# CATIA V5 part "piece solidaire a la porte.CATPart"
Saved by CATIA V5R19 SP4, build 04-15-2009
Part number: element accroché à la porte
Bounding box of the stored display mesh (mm): x -13.29 to 168.34, y -68.462 to 68.538, z -27 to 86.972
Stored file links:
  G:\EU_thinkMotion\CFAO_2010\MMS_groupe1\MMS_groupe1\A reprendre\OK\rdeneffle\piece solidaire a la porte.CATPart
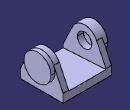
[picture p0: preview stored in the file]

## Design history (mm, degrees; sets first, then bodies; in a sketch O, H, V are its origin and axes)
Parameters
  `rayon element accroché a la porte` = 43 mm
  `rayon axe engrenage` = 21.1 mm
  LENGTH = 0 mm
Body1 (main body)
  Sketch1 on yz-plane, origin (0, 0, 0), H (0, 1, 0), V (0, 0, 1)
    line L1 (-68.4617, -27) -> (68.5383, -27)
    line L2 (68.5383, -27) -> (68.5383, 0)
    point P3 (68.5383, 0)
    line L3 (68.5383, 0) -> (38.8771, 62.4257)
    point P4 (68.5383, 0)
    point P5 (38.8771, 62.4257)
    arc A1 centre (0.0383, 43.9717) radius 43 from (-38.8005, 62.4257) to (38.8771, 62.4257) cw
    point P7 (0.0383, 43.9717)
    point P8 (38.8771, 62.4257)
    line L4 (-68.4617, -27) -> (-68.4617, 0)
    line L5 (-68.4617, 0) -> (-38.8005, 62.4257)
    length L1 = 137
    length L2 = 27
    radius A1 = 43 {= `rayon element accroché a la porte`}
    length L4 = 27
    distance P7 L2 = 68.5
    horizontal: L1 H
    vertical: L2 V, L4 V
    coincidence: P4 L2, A1 P5, P3 P4, P5 P8
    tangency: L5 A1, L3 A1
  Pad1: profile Sketch1, direction (1, 0, 0), length 155.05
  Sketch2 on start face of Pad1, origin (0, 0, 0), H (0, -1, 0), V (0, 0, 1)
    circle A1 centre (-0.0383, 43.9717) radius 43
    reference projected arc E1 centre (-0.0383, 43.9717) radius 43 from (42.9617, 43.9717) to (-42.2689, 52.0696) ccw from edge [start face of Pad1 | face of Pad1 from Sketch1.A1]
    radius A1 = 43
    concentricity: A1 E1
  Pad2: profile Sketch2, direction (-1, 0, 0), length 13.29
  Sketch3 on end face of Pad1, origin (155.05, 0, 0), H (0, 1, 0), V (0, 0, 1)
    circle A1 centre (0.0383, 43.9717) radius 43
    reference projected arc E1 centre (0.0383, 43.9717) radius 43 from (42.2689, 52.0696) to (-42.9617, 43.9717) ccw from edge [face of Pad1 from Sketch1.A1 | end face of Pad1]
    radius A1 = 43
    concentricity: A1 E1
  Pad3: profile Sketch3, direction (1, 0, 0), length 13.29
  Point1: (0, -6.5, 151.892)
  Plane1: type Tangent, Support face of Pad2, RefPoint Point1
  Sketch4 on Plane1, origin (0, 15.6114, 153.2316), H (1, 0, 0), V (0, -0.9982, -0.0605)
    line L1 (17.72, 94.8185) -> (137.33, 94.8185)
    line L2 (137.33, 94.8185) -> (137.33, -43.5635)
    line L3 (137.33, -43.5635) -> (17.72, -43.5635)
    line L4 (17.72, -43.5635) -> (17.72, 94.8185)
    reference projected line E1 (0, 94.8185) -> (155.05, 94.8185) from edge [face of Pad1 from Sketch1.L1 | face of Pad1 from Sketch1.L4]
    reference projected line E2 (0, -43.5635) -> (155.05, -43.5635) from edge [face of Pad1 from Sketch1.L3 | face of Pad1 from Sketch1.L2]
    distance L1 E1 = 0
    distance L3 E2 = 0
    horizontal: L1 H, L3 H
    vertical: L2 V, L4 V
  Pocket1: profile Sketch4, direction (0, 0.0605, -0.9982), length 158.594
  Sketch5 on face of Pocket1 from Sketch4.L2, origin (137.33, 0, 0), H (0, -1, 0), V (0, 0, 1)
    circle A1 centre (-0.0383, 43.9717) radius 23
    reference projected circle E1 centre (-0.0383, 43.9717) radius 43 from edge [face of Pad2 from Sketch2.A1 | end face of Pad2]
    radius A1 = 23
    concentricity: A1 E1
  Pocket2: profile Sketch5, direction (1, 0, 0), length 28
  Sketch6 on face of Pocket1 from Sketch4.L4, origin (17.72, 0, 0), H (0, 1, 0), V (0, 0, 1)
    circle A1 centre (0.0383, 43.9717) radius 23
    reference projected arc E1 centre (0.0383, 43.9717) radius 43 from (42.2689, 52.0696) to (-42.9617, 43.9717) ccw from edge [face of Pad1 from Sketch1.A1 | end face of Pad1]
    radius A1 = 23
    concentricity: A1 E1
  Pocket3: profile Sketch6, direction (-1, 0, 0), length 28
  Plane2: type Offset, RefPlane face of Pocket1 from Sketch4.L4, Offset 20
  Sketch7 on Plane2, origin (-2.28, 0, 0), H (0, -1, 0), V (0, 0, 1)
    circle A1 centre (-0.0383, 43.9717) radius 40
    reference projected arc E1 centre (-0.0383, 43.9717) radius 43 from (42.9617, 43.9717) to (-42.2689, 52.0696) ccw from edge [start face of Pad1 | face of Pad1 from Sketch1.A1]
    radius A1 = 40
    concentricity: A1 E1
  Pocket4: profile Sketch7, direction (-1, 0, 0), length 8
  Plane3: type Offset, RefPlane face of Pocket1 from Sketch4.L2, Offset 20
  Sketch8 on Plane3, origin (157.33, 0, 0), H (0, 1, 0), V (0, 0, 1)
    circle A1 centre (0.0383, 43.9717) radius 40
    reference projected arc E1 centre (0.0383, 43.9717) radius 43 from (42.2689, 52.0696) to (-42.9617, 43.9717) ccw from edge [face of Pad1 from Sketch1.A1 | end face of Pad1]
    radius A1 = 40
    concentricity: A1 E1
  Pocket5: profile Sketch8, direction (1, 0, 0), length 8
